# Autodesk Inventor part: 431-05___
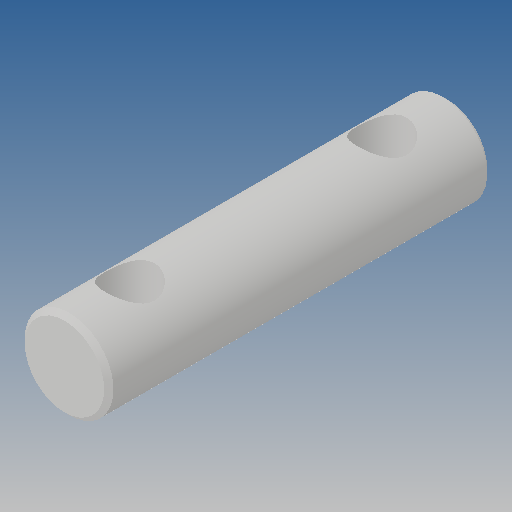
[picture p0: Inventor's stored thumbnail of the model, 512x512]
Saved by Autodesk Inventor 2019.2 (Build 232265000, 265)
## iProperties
Created: 2010-06
Part Number: 431-05___
Material: Ogólny
Document SubType Name: Modeling
Designer: CADENGINEERING4
Density: 1 g/cm^3
Appearance: Domyślna
Author: CADENGINEERING4
Revision Number: ANY
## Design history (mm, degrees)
feature "NONE"
node "Bryła1"
